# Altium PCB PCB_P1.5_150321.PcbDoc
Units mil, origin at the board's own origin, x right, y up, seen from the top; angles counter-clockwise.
Board outline 3081.38 x 1481.03 mil, 2 copper layers (Top Layer, Bottom Layer); 42 components, 37 nets, 195 pads, 0 vias.
Unrouted connection lines stored in the file: 94.
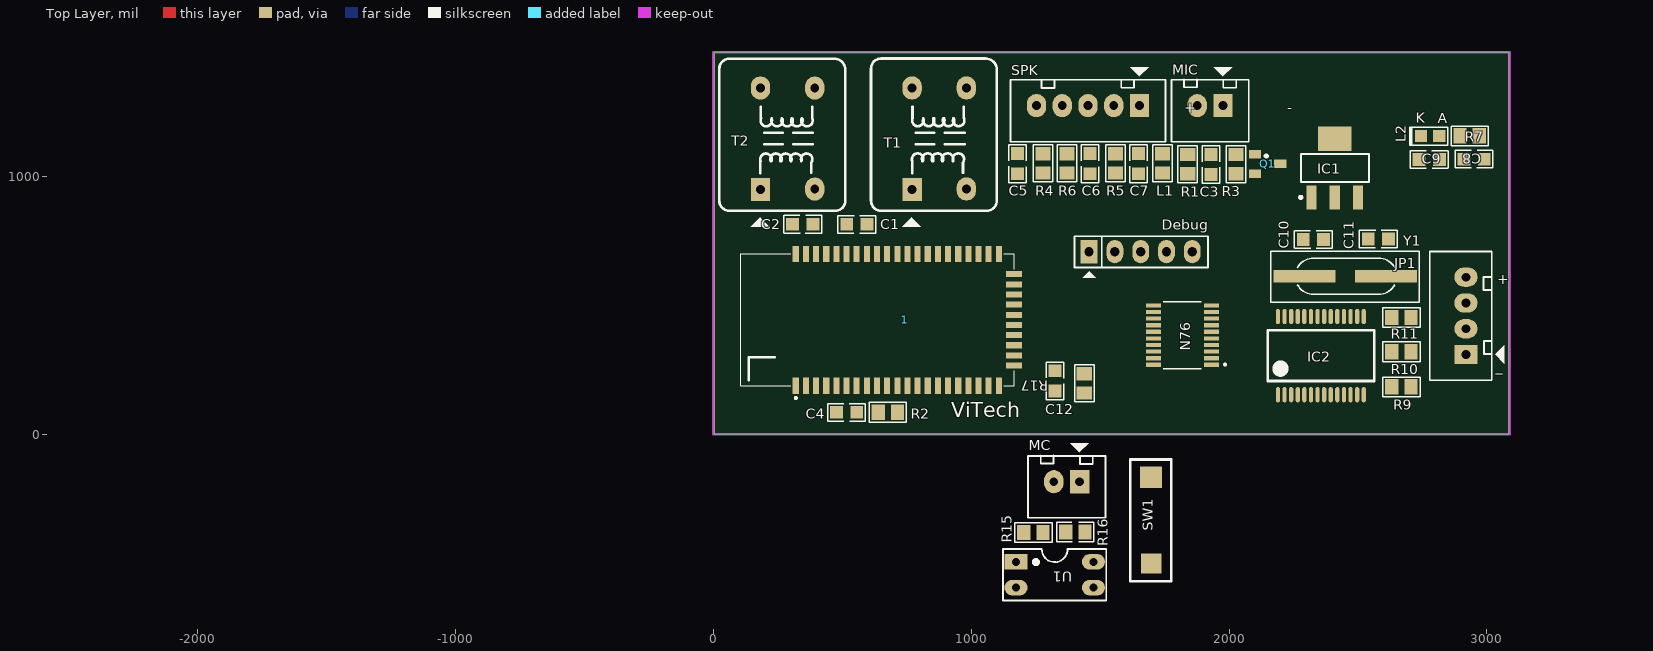
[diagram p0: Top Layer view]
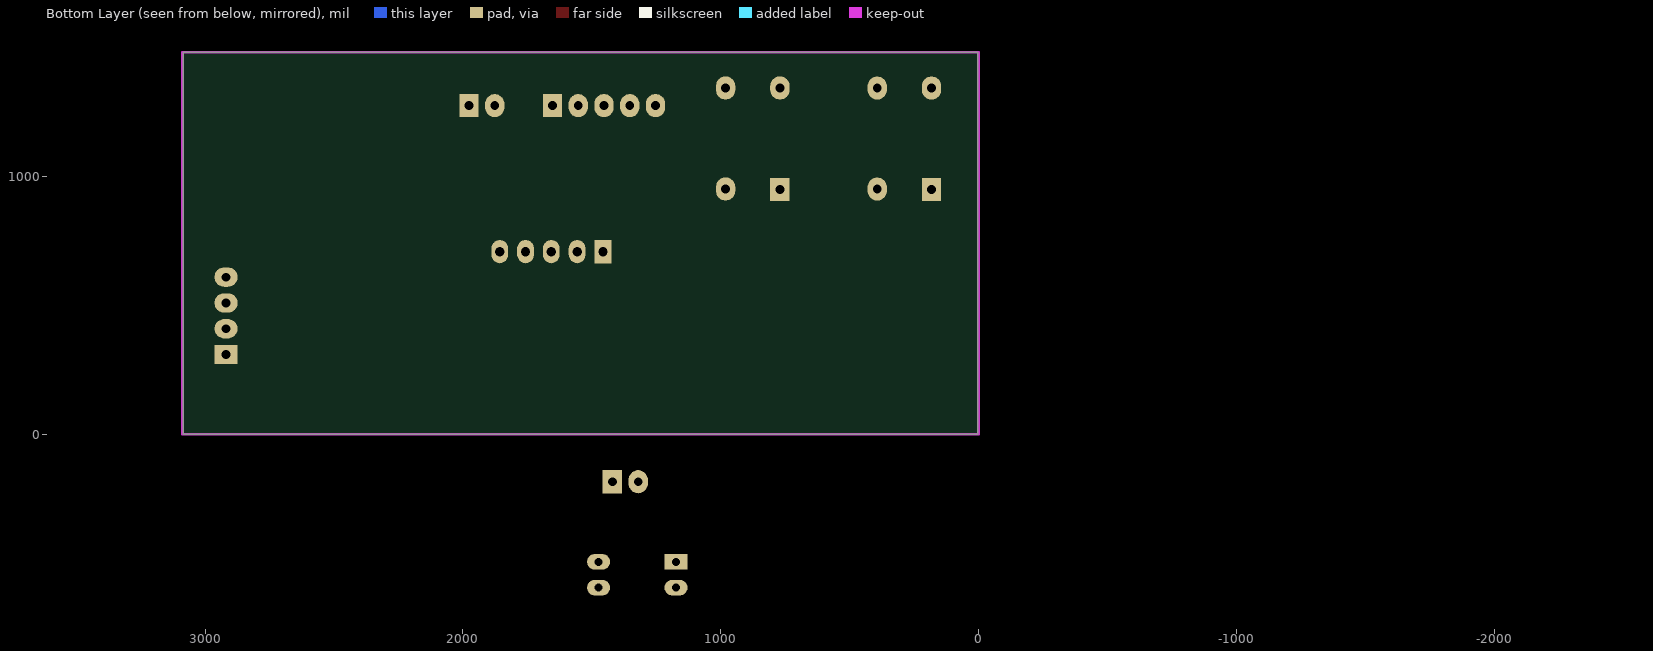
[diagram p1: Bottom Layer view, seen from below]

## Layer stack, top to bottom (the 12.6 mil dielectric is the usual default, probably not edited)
Top Solder: solder mask 0.4, Solder Resist, Dk 3.5
Top Layer: signal copper 1.4
Dielectric 1: dielectric 12.6, FR-4, Dk 4.8
Bottom Layer: signal copper 1.4
Bottom Solder: solder mask 0.4, Solder Resist, Dk 3.5

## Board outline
3.86,0.5 3085.24,0.5 3085.24,1481.53 3.86,1481.54

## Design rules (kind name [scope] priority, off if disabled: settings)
Clearance [All] p1: gap=1 ignorepadtopadclearanceinfootprint=FALSE
PolygonConnect vias_connect [IsNamedPolygon('GND') vs Isvia] p1: connectstyle=Direct reliefconductorwidth=10 reliefentries=4 polygonreliefangle="90 Angle" airgapwidth=10
PolygonConnect Pad_connect [All] p2: connectstyle=Relief reliefconductorwidth=11 reliefentries=4 polygonreliefangle="90 Angle" airgapwidth=11
RoutingVias [InNet('GND_BT')] p1: holewidth=15.75 width=31.5 viastyle="Through Hole" minholewidth=15.75 minwidth=31.5 maxholewidth=15.75 maxwidth=31.5
SolderMaskExpansion [All] p1: expansion=4 istentingtop=FALSE
Width [All] p1: maxlimit=30 minlimit=11 preferedwidth=15
30 further rules are at their usual default settings.

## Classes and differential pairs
net class Undefined: CLK DAT RX0 RX_PL

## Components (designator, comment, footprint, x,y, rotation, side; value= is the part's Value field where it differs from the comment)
1 "FSC-BT806" FSCBT806 652.15,434.02 r90 top locked
C1 "0.1µF" CAP_0805 556.3,814.53 r0 top
C2 "0.1µF" CAP_0805 346.73,814.72 r180 top
C3 "1uF" CAP_0805 1929.03,1046.48 r270 top
C4 "100nF" CAP_0805 516.32,85.48 r0 top
C5 "0.1µF" CAP_0805 1180.02,1049.75 r90 top
C6 "0.1µF" CAP_0805 1461.18,1049.75 r90 top
C7 "15pF" CAP_0805 1648.61,1049.75 r90 top
C8 "1uF" CAP_0805 2949.92,1066.89 r180 top
C9 "4.7uF" CAP_0805 2775.75,1066.02 r0 top
C10 "22pF" CAP_0805 2326.68,755.62 r180 top
C11 "22pF" CAP_0805 2578.73,758.04 r0 top
C12 "0.1uF" CAP_0805 1325.32,207.17 r270 top
Debug "JP5" JP5 1456.89,708.46 r0 top
IC1 "LM1117" SOT223-4N 2409.69,1032.8 r90 top value=LM317
IC2 "PL2303HX" PL2303 2189.34,153.66 r0 top value=PL2303
JP1 "" CON4 2918.36,309.61 r90 top value="Connector 4"
L1 "15nH" RES_0805 1741.75,1051.12 r90 top
L2 "" LED_0805 2779.6,1156.56 r0 top
MC "" CON2 1420.2,-183.65 r180 top value="Connector 2"
MIC "JP2" CON2 1976.38,1274.77 r180 top value="Connector 2"
N76 "N76E003AT20" SOP65P640X120-20N 1818.86,384.81 r180 top (schematic designator U)
Q1 "SI2302" SOT23A 2149.06,1049.41 r270 top
R1 "10K" RES_0805 1839.32,1047.84 r90 top
R2 "10K" RES_0805 676.68,85.48 r180 top
R3 "10K" RES_0805 2026.75,1047.85 r270 top
R4 "1K" RES_0805 1277.73,1051.12 r270 top
R5 "2.2K" RES_0805 1558.89,1051.12 r90 top
R6 "1K" RES_0805 1371.45,1051.12 r270 top
R7 "1K" RES_0805 2932.59,1157.52 r0 top
R9 "1.5K" RES_0805 2668.39,184.29 r180 top
R10 "100R" RES_0805 2668.39,320.12 r0 top
R11 "100R" RES_0805 2668.39,453.07 r0 top
R15 "100R" RES_0805 1241.19,-381.19 r0 top
R16 "100R" RES_0805 1403.62,-379.06 r0 top
R17 "10K" RES_0805 1438.43,197.83 r90 top
SPK "JP5" CON5 1652.65,1274.77 r180 top value="Connector 5"
SW1 "" SW_342_SMD 1697.48,-501.06 r270 top
T1 "T_Adio" T_Adito 827.56,1142.52 r90 top value=BAX
T2 "T_Adio" T_Adito 239.57,1142.13 r90 top value=BAX
U1 "PC817" DIP4/W0.3 1173.58,-494.46 r270 top
Y1 "12MHz" XTAL_314_240X47_SMD 2607.63,613.39 r180 top

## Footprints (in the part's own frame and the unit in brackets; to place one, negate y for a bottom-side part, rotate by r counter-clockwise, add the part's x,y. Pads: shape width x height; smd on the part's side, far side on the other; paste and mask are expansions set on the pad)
CAP_0805 [mil] "Ceramic Capacitor"
  rect 50x50 smd mask+3: 1(-39.37,0) 2(39.37,0)
  silkscreen extent -73,-34 73,34, body extent -39,-25 39,25, height 31
CON2 [mil] "CON2"
  rect 75x90 hole 34: 1(0,0)
  oval 75x90 hole 34: 2(100,0)
  silkscreen extent -100,-150 200,140, body extent -68,-70 168,107, height 236
CON4 [mil] "B1205S"
  rect 75x90 hole 34: 1(0,0)
  oval 75x90 hole 34: 2(100,0) 3(200,0) 4(300,0)
  silkscreen extent -100,-150 400,140, body extent -90,-90 398,136, height 276
CON5 [mil] "CON5"
  rect 75x90 hole 34: 1(0,0)
  oval 75x90 hole 34: 2(100,0) 3(200,0) 4(300,0) 5(400,0)
  silkscreen extent -100,-150 500,140, body extent -101,-98 496,125, height 288
DIP4/W0.3 [mil] "4 PIN, W 300mil, Pin to pin 100mil"
  rect 60x90 hole 31: 1(0,0)
  oval 60x90 hole 31: 2(100,0) 3(100,300) 4(0,300)
  silkscreen extent -50,-50 150,350, body extent -59,-10 159,305, height 170
FSCBT806 [mm]
  rect 1.6x0.6 smd: 1(-6.25,8.45) 2(-6.25,7.45) 3(-6.25,6.45) 4(-6.25,5.45) 5(-6.25,4.45) 6(-6.25,3.45) 7(-6.25,2.45) 8(-6.25,1.45) 9(-6.25,0.45) 10(-6.25,-0.55) 11(-6.25,-1.55) 12(-6.25,-2.55) 13(-6.25,-3.55) 14(-6.25,-4.55) 15(-6.25,-5.55) 16(-6.25,-6.55) 17(-6.25,-7.55) 18(-6.25,-8.55) 19(-6.25,-9.55) 20(-6.25,-10.55) 21(-6.25,-11.55) 32(6.75,-11.55) 33(6.75,-10.55) 34(6.75,-9.55) 35(6.75,-8.55) 36(6.75,-7.55) 37(6.75,-6.55) 38(6.75,-5.55) 39(6.75,-4.55) 40(6.75,-3.55) 41(6.75,-2.55) 42(6.75,-1.55) 43(6.75,-0.55) 44(6.75,0.45) 45(6.75,1.45) 46(6.75,2.45) 47(6.75,3.45) 48(6.75,4.45) 49(6.75,5.45) 50(6.75,6.45) 51(6.75,7.45) 52(6.75,8.45)
  rect 0.6x1.6 smd: 22(-4.25,-13.05) 23(-3.25,-13.05) 24(-2.25,-13.05) 25(-1.25,-13.05) 26(-0.25,-13.05) 27(0.75,-13.05) 28(1.75,-13.05) 29(2.75,-13.05) 30(3.75,-13.05) 31(4.75,-13.05)
  silkscreen extent -7.55,-13.05 6.75,13.85, body extent -6.22,-13.08 6.73,13.84, height 0.25
JP5 [mil] "JP5"
  rect 65x90 hole 36: 1(0,0)
  oval 65x90 hole 36: 2(100,0) 3(200,0) 4(300,0) 5(400,0)
  silkscreen extent -57,-101 461,60, body extent -48,-53 448,45, height 323
LED_0805 [mm] "LED"
  rect 1.2x1.2 smd mask+0.076: A(0.889,0) K(-0.889,0)
  silkscreen extent -1.99,-0.89 1.73,0.89, body extent -1.01,-0.62 1.01,0.63, height 1.1
PL2303 [mil] "PL2303"
  oval 16.53x59.03 smd mask+7.9: 1(0,0) 2(25.6,0) 3(51.18,0) 4(76.78,0) 5(102.37,0) 6(127.97,0) 7(153.57,0) 8(179.15,0) 9(204.75,0) 10(230.35,0) 11(255.93,0) 12(281.53,0) 13(307.12,0) 14(332.7,0) 15(332.7,303.18) 16(307.12,303.18) 17(281.53,303.18) 18(255.93,303.18) 19(230.35,303.18) 20(204.75,303.18) 21(179.15,303.18) 22(153.57,303.18) 23(127.97,303.18) 24(102.37,303.18) 25(76.78,303.18) 26(51.18,303.18) 27(25.6,303.18) 28(0,303.18)
  silkscreen extent -40,53 373,250
RES_0805 [mm] "Resister"
  rect 1.3x1.5 smd mask+0.076: 1(0.95,0) 2(-0.95,0)
  silkscreen extent -1.83,-0.97 1.83,0.97, body extent -1,-0.63 1,0.62, height 0.5
SOP65P640X120-20N [mm]
  rrect10% 1.48x0.41 smd: 1(-2.865,2.925) 2(-2.865,2.275) 3(-2.865,1.625) 4(-2.865,0.975) 5(-2.865,0.325) 6(-2.865,-0.325) 7(-2.865,-0.975) 8(-2.865,-1.625) 9(-2.865,-2.275) 10(-2.865,-2.925) 11(2.865,-2.925) 12(2.865,-2.275) 13(2.865,-1.625) 14(2.865,-0.975) 15(2.865,-0.325) 16(2.865,0.325) 17(2.865,0.975) 18(2.865,1.625) 19(2.865,2.275) 20(2.865,2.925)
  silkscreen extent -4.3,-3.3 1.87,3.3
SOT23A [mm] "SOT 23A"
  rect 0.85x1.2 smd: 1(-0.94,-1.245) 2(0.005,1.25) 3(0.985,-1.25)
  silkscreen extent -0.88,-0.25 -0.64,0, body extent -1.5,-1.3 1.5,1.2, height 1.06
SOT223-4N [mm] "SOT223, 4-Leads, Body 6.5x3.5mm, Pitch 2.3mm, Lead Span 7mm, IPC Medium Density"
  rect 2.4x1 smd: 1(-2.9,2.3) 2(-2.9,0) 3(-2.9,-2.3)
  rect 2.4x3.3 smd: 4(2.9,0)
  silkscreen extent -3.02,-3.35 1.4,3.47, body extent -3.39,-3.27 3.5,3.23, height 1.72
SW_342_SMD [mm] "CASE: SMD"
  rect 2x2 smd: 1(0,0)
  rect 2.15x2.15 smd: 2(-8.5,0)
  silkscreen extent -10.25,-2.06 1.75,2, body extent -7.17,-1.79 -1.17,1.71, height 2.4
T_Adito [mil]
  rect 90x75 hole 34: 1(-192.91,57.09)
  oval 90x75 hole 34: 2(-190.94,-153.54) 3(200.79,-153.54) 4(200.79,57.09)
  silkscreen extent -337,-272 315,217
XTAL_314_240X47_SMD [mm] "CASE: TH"
  rect 6.096x1.2 smd: 1(0,0) 2(8,0)
  silkscreen extent -3.29,-2.44 11.32,2.57, body extent -2.99,-2.27 10.9,2.41, height 3.05

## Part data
C1 C2 C5 C6 C7 C12: library part CAP_0.1uF-50V-5%-0805, "0.1µF ±5% 50V Ceramic Capacitor X7R 0805 (2012 Metric)", Case/Package="0805 (2012 Metric)", Manufacturer=KEMET, Manufacturing Part Number=C0805C104J5RACTU, Supplier Part Number-1=399-1171-1-ND
C3 C8: library part CAP_1uF-50V-5%-0805, "1µF ±5% 50V Ceramic Capacitor X7R 0805 (2012 Metric)", Case/Package="0805 (2012 Metric)", Manufacturer=Yageo, Manufacturing Part Number=CC0805JKX7R9BB105, Supplier Part Number-1=311-3498-1-ND
C4: library part CAP_1uF-50V-5%-0805, "100µF ±5% 50V Ceramic Capacitor X7R 0805 (2012 Metric)", Case/Package="0805 (2012 Metric)", Manufacturer=Yageo, Manufacturing Part Number=CC0805JKX7R9BB105, Supplier Part Number-1=311-3498-1-ND
C9: library part CAP_1uF-50V-5%-0805, "4.7µF ±5% 50V Ceramic Capacitor X7R 0805 (2012 Metric)", Case/Package="0805 (2012 Metric)", Manufacturer=Yageo, Manufacturing Part Number=CC0805JKX7R9BB105, Supplier Part Number-1=311-3498-1-ND
C10 C11: library part CAP_22pF-50V-5%-0805, "22pF ±5% 50V Ceramic Capacitor C0G, NP0 0805 (2012 Metric)", Case/Package=0805, Manufacturer=KEMET, Manufacturer Part Number=C0805C220J5GACTU, Supplier Part Number-1=399-1113-1-ND
IC1: "Available in 1.8V, 2.5V, 2.85V, 3.3V, 5V, and  Adjustable Versions"
IC2: "USB - RS232 Converter"
JP1: library part Con4, "Connector 4"
L1: library part RES_1K-0.125W-1%-0805, "Conductor 15nH", Case/Package=0805, Manufacturer=垈㎵á, Manufacturer Part Number=RC0805FR-071KL, Supplier Part Number-1=311-1.00KCRCT-ND
L2: library part LED-RED_10mA-0805, "Red 621nm LED Indication - Discrete 2V 0805 (2012 Metric)", Case/ Package=0805, Manufacturer="Lite-On Inc.", Manufacturer Part Number=LTST-C170EKT, Supplier Part Number-1=160-1178-1-ND
MC MIC: library part Con2, "Connector 2"
N76: "8051 N76 Microcontroller IC 8-Bit 16MHz 18KB _18K x 8_ FLASH 20-TSSOP", Package="TSSOP-20 Nuvoton Technology"
Q1: library part DV3
R1 R2 R3 R4 R6: library part RES_10K-0.125W-1%-0805_1, "10 kOhms ±1% 0.125W, 1/8W Chip Resistor 0805 (2012 Metric) Moisture Resistant Thick Film", Case/Package=0805, Manufacturer=Yageo, Manufacturing Part Number=RC0805FR-0710KL, Supplier Part Number-1=311-10.0KCRCT-ND
R5: library part RES_10K-0.125W-1%-0805_1, "2.2kOhms ±1% 0.125W, 1/8W Chip Resistor 0805 (2012 Metric) Moisture Resistant Thick Film", Case/Package=0805, Manufacturer=Yageo, Manufacturing Part Number=RC0805FR-0710KL, Supplier Part Number-1=311-10.0KCRCT-ND
R7: library part RES_10K-0.125W-1%-0805_1, "1 kOhms ±1% 0.125W, 1/8W Chip Resistor 0805 (2012 Metric) Moisture Resistant Thick Film", Case/Package=0805, Manufacturer=Yageo, Manufacturing Part Number=RC0805FR-0710KL, Supplier Part Number-1=311-10.0KCRCT-ND
R9: library part RES_1.5K-0.125W-1%-0805, "1.5 kOhms ±1% 0.125W, 1/8W Chip Resistor 0805 (2012 Metric) Thick Film", Case/Package=0805, Manufacturer="TE Connectivity Passive Product", Manufacturing Part Number=CRG0805F1K5, Supplier Part Number-1=A106057CT-ND
R10 R11: library part RES_0ohm-0.125W-1%-0805_1, "1000Ohms ±1% 0.125W, 1/8W Chip Resistor 0805 (2012 Metric) Moisture Resistant Thick Film", Case/Package=0805, Manufacturer=垈㎵á, Manufacturer Part Number=RC0805FR-071KL, Supplier Part Number-1=311-1.00KCRCT-ND
R15 R16: library part RES_1K-0.125W-1%-0805, "1 kOhms ±1% 0.125W, 1/8W Chip Resistor 0805 (2012 Metric) Moisture Resistant Thick Film", Case/Package=0805, Manufacturer=垈㎵á, Manufacturer Part Number=RC0805FR-071KL, Supplier Part Number-1=311-1.00KCRCT-ND
R17: library part RES_10MOHM-0.125W-1%-0805, "10K ±1% 0.125W, 1/8W Chip Resistor 0805 (2012 Metric) Automotive AEC-Q200, High Voltage Thick Film", Case/Package="0805 (2012 Metric)", Manufacturer="Rohm Semiconductor", Manufacturing Part Number=KTR10EZPF1005, Supplier Part Number-1=RHM10.0MAHCT-ND
SPK: library part Con5, "Connector 5"
SW1: library part SW_KSR223GLFG-SMD, "Tactile Switch SPST-NO Top Actuated Surface Mount", Case/Package=SMD, Manufacturer=C&K, Manufacturing Part Number=KSR223GLFG, Supplier Part Number-1=401-1704-1-ND
T1 T2: "Transformer Audio"
U1: "Single Opto"
Y1: library part XTAL_8MHZ-LFXTAL030234, "Crystals 8MHz 22pF -20C 70C", Case/Package=SMD, Manufacturer="IQD Frequency Products", Manufacturing Part Number=LFXTAL030234Reel, Supplier Part Number-1=449-LFXTAL030234REEL

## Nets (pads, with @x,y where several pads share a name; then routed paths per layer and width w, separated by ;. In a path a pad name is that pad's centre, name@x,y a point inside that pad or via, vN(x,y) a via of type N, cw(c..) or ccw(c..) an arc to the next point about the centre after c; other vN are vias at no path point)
3V3: 1.33 C3.2 C9.2 Debug.5 IC1.2 N76.9 R1.2 R2.2 R17.2 U1.4
3V3_PL2303: IC2.17 R9.1
CLK: 1.13 Debug.3 N76.18
DAT: 1.14 Debug.4 N76.8
DC_CHECK: N76.14 R16.1 U1.3
GND_BT: 1.1 1.22 1.32 1.50 1.52 C4.1 C7.2 C8.1 C9.1 C10.2 C11.1 C12.1 Debug.1 IC1.1 IC2.7 IC2.18 IC2.21 IC2.25 IC2.26 JP1.1 L2.K MIC.1 Q1.3 R3.1 R16.2 SW1.1 U1.2
Net1_8: 1.8 C4.2 R2.1
Net1_34: 1.34 Q1.2 R1.1
Net1_43: 1.43 R6.1
Net1_44: 1.44 R4.1
Net1_45: 1.45 C5.1 R5.1
Net1_47: 1.47 C1.1
Net1_48: 1.48 T1.2 T2.2
Net1_49: 1.49 C2.1
NetC1_2: C1.2 T1.1
NetC2_2: C2.2 T2.1
NetC3_1: C3.1 Q1.1 R3.2
NetC5_2: C5.2 R4.2
NetC6_1: C6.1 C7.1 L1.2 R5.2
NetC6_2: C6.2 R6.2
NetC10_1: C10.1 IC2.28 Y1.2
NetC11_2: C11.2 IC2.27 Y1.1
NetIC2_15: IC2.15 R9.2 R10.2
NetIC2_16: IC2.16 R11.2
NetJP1_2: JP1.2 R10.1
NetJP1_3: JP1.3 R11.1
NetL1_1: L1.1 MIC.2
NetL2_A: L2.A R7.2
NetMC_1: MC.1 MC.2 R15.1
NetR15_2: R15.2 U1.1
NetSPK_1: SPK.1 SPK.2 T1.3
NetSPK_3: SPK.3 T1.4 T2.4
NetSPK_4: SPK.4 SPK.5 T2.3
NRST: C12.2 Debug.2 N76.4 R17.1 SW1.2
RX0: IC2.1 N76.3
RX_PL: IC2.5 N76.2
VCC: C8.2 IC1.3 IC2.4 IC2.20 JP1.4 R7.1
pads on no net: 1.2 1.3 1.4 1.5 1.6 1.7 1.9 1.10 1.11 1.12 1.15 1.16 1.17 1.18 1.19 1.20 1.21 1.23 1.24 1.25 1.26 1.27 1.28 1.29 1.30 1.31 1.35 1.36 1.37 1.38 1.39 1.40 1.41 1.42 1.46 1.51 IC1.4 IC2.2 IC2.3 IC2.6 IC2.8 IC2.9 IC2.10 IC2.11 IC2.12 IC2.13 IC2.14 IC2.19 IC2.22 IC2.23 IC2.24 N76.1 N76.5 N76.6 N76.7 N76.10 N76.11 N76.12 N76.13 N76.15 N76.16 N76.17 N76.19 N76.20

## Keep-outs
Keep-Out Layer:
  lines w10: 0,0 3087.72,0 3087.72,1481.5 0,1481.5 0,0

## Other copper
Top Layer:
  pour cut-out: -731.31,1186.33 -731.31,827.42 -1277.61,827.42 -1277.61,-162.3 -2187.68,-162.3 -2187.68,-298.33 -2478.47,-298.33 -2478.47,1182.33
  pour cut-out: 3268.31,1246.94 3268.31,829.32 3506.85,829.32 3506.85,1247.69

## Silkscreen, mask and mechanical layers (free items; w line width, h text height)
Top Overlay:
  text "+" at 1826.73,1247.09 h39.37
  text "-" at 2224.92,1247.13 h39.37
  text "+" at 3038.94,582.17 h39.37
  text "_" at 3034.17,244.76 h39.37
  text "ViTech" at 921.5,46.54 h100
